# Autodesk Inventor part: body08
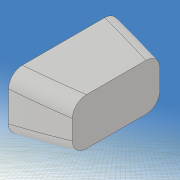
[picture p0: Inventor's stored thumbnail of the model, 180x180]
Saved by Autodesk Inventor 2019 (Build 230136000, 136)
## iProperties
Created: 2020-12
Part Number: body08
Material: 一般
Document SubType Name: Modeling
Designer: kikut
Density: 1 g/cm^3
Appearance: 既定
Mass: 87.6477 g
Surface Area: 156.124 cm^2
Volume: 87.6477 cm^3
Author: kikut
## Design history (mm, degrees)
sketch "スケッチ1"
  geometry: L1 (-100, -20)-(100, -20); L2 (100, -20)-(100, 20); L3 (100, 20)-(-100, 20); L4 (-100, 20)-(-100, -20); L5 (-100, -20)-(100, 20); L6 (100, -20)-(-100, 20); 1 further point
  constraints: 12 end point, 2 midpoint, 2 parallel, 1 horizontal, 1 perpendicular
  dimensions: "d0" = 40 distance of L3.end L1.start; "d1" = 200 distance of L2.end L3.end
extrude "押し出し1" new body sketch "スケッチ1" stored distance "d2" = 60; taper "d3" = 0 deg
sketch "スケッチ2"
  geometry: L1 (0, -60)-(0, 0) reference; L2 (200, -60)-(200, 0) reference; L3 (0, 0)-(200, 0) reference; L4 (200, -60)-(0, -60) reference; L5 (0, -26)-(0, -32); L6 (194, -10)-(194, -13); L7 (194, -13)-(174, -33); L8 (174, -33)-(200, -58); L9 (-20, 20)-(220, 20); L10 (220, 20)-(220, -100); L11 (220, -100)-(-20, -100); L12 (-20, -100)-(-20, 20); 12 further points
  constraints: 16 end point, 4 point on line, 2 parallel, 2 vertical, 1 horizontal, 1 perpendicular, 14 other
  dimensions: "d4" = 32 distance from line of point (32, -12) L1; "d5" = 50 horizontal distance of point (32, -12) point (82, -11); "d6" = 50 horizontal distance of point (132, -17) point (82, -11); "d7" = 12 distance from line of point (32, -12) L3; "d8" = 11 distance from line of point (82, -11) L3; "d10" = 17 distance from line of point (132, -17) L3; "d11" = 26 distance from line of L5.start L3; "d12" = 0 distance from line of point (200, -60) L4; "d13" = 28 distance from line of L5.end L4; "d14" = 12 distance from line of point (28, -48) L4; "d15" = 10 distance from line of point (80, -50) L4; "d16" = 16 distance from line of point (130, -44) L4; "d17" = 28 distance from line of point (28, -48) L1; "d19" = 50 horizontal distance of point (130, -44) point (80, -50); "d20" = 80 distance from line of point (80, -50) L1; "d21" = 6 distance from line of L6.start L2; "d22" = 36 distance from line of point (164, -24) L2; "d23" = 24 distance from line of point (176, -20) L2; "d24" = 10 distance from line of L6.start L3; "d25" = 20 distance from line of point (176, -20) L3; "d26" = 24 distance from line of point (164, -24) L3; "d27" = 40 distance from line of point (160, -40) L2; "d28" = 25 distance from line of point (175, -47.5) L2; "d29" = 12.5 distance from line of point (175, -47.5) L4; "d30" = 20 distance from line of L4 point (160, -40); "d31" = 3 distance of L6.start L6.end; "d32" = 33 distance from line of L7.end L3; "d33" = 26 distance from line of L7.end L2; "d34" = 2 distance of L8.end L2.start; "d35" = 120 distance of L11.end L9.start; "d36" = 240 distance of L10.end L11.end; "d37" = 20 distance between parallel lines of L1 L12; "d38" = 20 distance between parallel lines of L3 L9
extrude "押し出し2" cut sketch "スケッチ2" extent not by distance; stored distance "d39" = 0.02; taper "d40" = 0 deg
sketch "スケッチ8"
  geometry: L1 (-100, -20)-(-100, 20) reference; L2 (100, 20)-(100, -20) reference; L3 (-142.805, 0)-(142.831, 0) reference; L4 (110, 30)-(-110, 30); L5 (-110, 30)-(-110, -30); L6 (-110, -30)-(110, -30); L7 (110, -30)-(110, 30); L8 (110, 30)-(-110, -30); L9 (-110, 30)-(110, -30); L10 (-100, -2)-(-100, 2); L11 (100, -3)-(100, 3); 7 further points
  constraints: 16 end point, 4 point on line, 2 midpoint, 2 parallel, 2 perpendicular, 1 collinear, 1 horizontal, 10 other
  dimensions: "d93" = 2 vertical distance of point (0, 0) L10.end; "d94" = 2 vertical distance of L10.start point (0, 0); "d95" = 35 distance from line of point (-65, -10) L1; "d96" = 0 horizontal distance of point (-65, 10) point (-65, -10); "d97" = 10 vertical distance of point (0, 0) point (-65, -10); "d98" = 10 vertical distance of point (-65, 10) point (0, 0); "d99" = 100 distance from line of point (0, -10) L1; "d100" = 0 horizontal distance of point (0, 10) point (0, -10); "d101" = 10 distance of point (0, -10) point (0, 0); "d102" = 10 distance of point (0, 0) point (0, 10); "d103" = 160 distance from line of point (60, -4) L1; "d104" = 0 horizontal distance of point (60, 4) point (60, -4); "d105" = 4 distance from line of L3 point (60, -4); "d106" = 4 distance from line of L3 point (60, 4); "d107" = 3 distance from line of L11.start L3; "d108" = 3 distance from line of L11.end L3; "d109" = 220 distance of L5.end L6.end; "d110" = 60 distance of L4.end L5.end
extrude "押し出し6" cut sketch "スケッチ8" extent not by distance; stored distance "d111" = 10; taper "d112" = 0 deg
sketch "スケッチ9" dims "d113" = 20, "d114" = 12
  geometry: L1 (-29, -18)-(21, -18); L2 (21, -18)-(21, 22); L3 (21, 22)-(-29, 22); L4 (-29, 22)-(-29, -18); L5 (-29, -18)-(21, 22); L6 (21, -18)-(-29, 22); 2 further points; 1 other entity
  constraints: 12 end point, 2 midpoint, 2 parallel, 1 coincident, 1 horizontal, 1 perpendicular, 2 other
  dimensions: "d115" = 50 distance of L2.end L3.end; "d116" = 40 distance of L1.end L2.end
extrude "押し出し7" cut sketch "スケッチ9" distance "d117" = 150; taper "d118" = 0 deg
fillet "フィレット4" dims "d119" = 4
fillet "フィレット5" dims "d120" = 4
fillet "フィレット6" dims "d121" = 2
node "作業平面2"
sketch "スケッチ10"
  geometry: L1 (0, -41.439)-(0, 38.458) reference; L2 (141.833, 0)-(-140.631, 0) reference; L3 (82.55, 12.983)-(81.45, -4.983); A1 r 9 centre (82, 4) between (82.55, 12.983) and (81.45, -4.983); 1 further point
  constraints: 2 end point, 2 point on circle, 1 centre point
  dimensions: "d123" = 82 distance from line of L1 A1.centre; "d124" = 4 distance from line of L2 A1.centre; "d125" = 9 radius of A1; "d126" = 180 deg dimension on A1.centre L3.end L3.start; "d127" = 90 deg dimension on L3.end point (0, 0) A1.centre
revolve "回転1" sketch "スケッチ10" stored, may be unused: angle "d128" = 90 deg
mirror "ミラー1"
sketch "スケッチ11"
  geometry: L1 (-20, 30)-(-35, 30); L2 (-35, 30)-(-35, -30); L3 (-35, -30)-(-20, -30); L4 (-20, -30)-(-20, 30); L5 (0, -40.648)-(0, 34.486) reference; L6 (140.69, 0)-(-139.196, 0) reference; L7 (120, 53.792)-(-120, 53.792); L8 (-120, 53.792)-(-120, -46.208); L9 (-120, -46.208)-(120, -46.208); L10 (120, -46.208)-(120, 53.792); 1 further point
  constraints: 16 end point, 4 parallel, 2 horizontal, 2 perpendicular, 2 other
  dimensions: "d130" = 15 distance of L1.start L1.end; "d131" = 60 distance of L3.end L1.start; "d132" = 100 distance of L9.end L7.start; "d133" = 240 distance of L7.start L7.end; "d137" = 35 distance between parallel lines of L2 L5
extrude "押し出し8" cut sketch "スケッチ11" stored distance "d134" = 40; taper "d135" = 0 deg
node "ソリッド1"
other parameters: "d122" = -1
